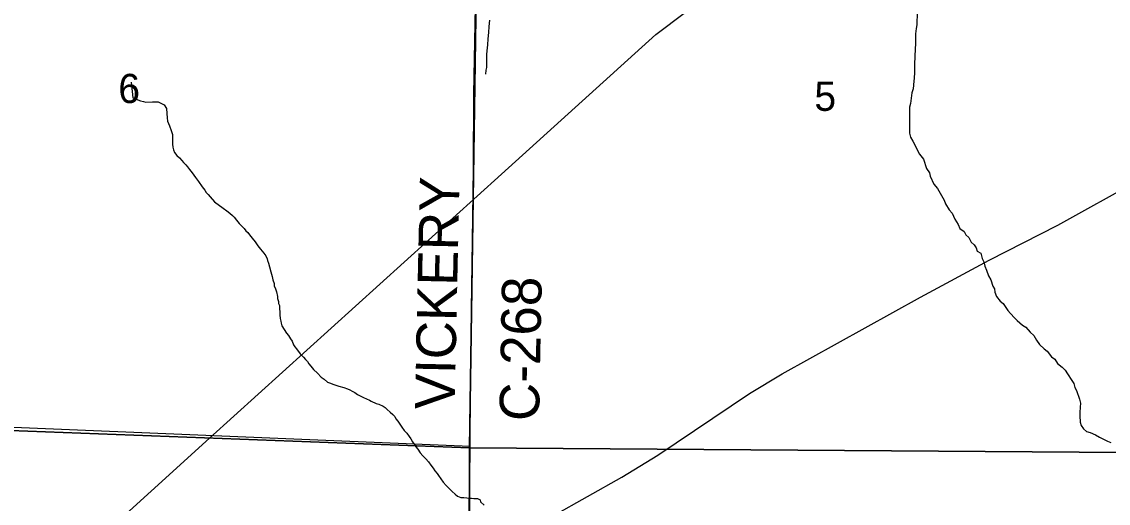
# Model space of a CAD drawing. Extents: x -8.5 to 18.7, y -20.3 to 7.
# Drawn here: x 12.261 to 15.375, y -1.005 to 0.375 of the extents above; entities that cross this region are included whole.
import ezdxf

# ---------------------------------------------------------------- set-up
doc = ezdxf.new("R2010")
doc.units = 0
for name, color, linetype in [('GM_X_County_Road', 7, 'Continuous'), ('GM_X_County_Road_Text', 7, 'Continuous'), ('GM_X_Minor_River', 7, 'Continuous'), ('GM_X_Rail_Line', 7, 'Continuous'), ('GM_X_Section', 7, 'Continuous'), ('GM_X_Section_Text', 7, 'Continuous'), ('GM_X_State_Route', 7, 'Continuous'), ('GM_X_Township_Road', 7, 'Continuous')]:
    doc.layers.add(name, color=color, linetype=linetype)

msp = doc.modelspace()

# ---------------------------------------------------------------- linework, layer by layer
at = {"layer": 'GM_X_County_Road'}
msp.add_lwpolyline([(13.5429, -1.1774), (13.5457, -1.1129), (13.546, -0.9367), (13.5466, -0.8416), (13.548, -0.6795), (13.55, -0.4503), (13.553, -0.2515), (13.5558, -0.0456), (13.5572, 0.1676), (13.5612, 0.3695), (13.5648, 0.5662), (13.5704, 0.8181), (13.5752, 1.0646), (13.5783, 1.1785), (13.5804, 1.1936)], dxfattribs=at)
at = {"layer": 'GM_X_Minor_River'}
for points in [[(13.6024, 0.3796), (13.6002, 0.3613), (13.5988, 0.3446), (13.5974, 0.3264), (13.5959, 0.3089), (13.5945, 0.2922), (13.5938, 0.2808), (13.5938, 0.2755), (13.5931, 0.2701), (13.5932, 0.2496), (13.5932, 0.2436), (13.5917, 0.2367), (13.591, 0.2253)], [(14.8276, 0.4028), (14.8263, 0.3664), (14.8248, 0.3557), (14.8226, 0.3405), (14.8227, 0.3185), (14.8221, 0.2911), (14.8214, 0.282), (14.8207, 0.2714), (14.82, 0.2577), (14.8201, 0.2296), (14.8187, 0.2136), (14.818, 0.2045), (14.8158, 0.1832), (14.8128, 0.1711), (14.8084, 0.1407), (14.8062, 0.13), (14.8055, 0.1125), (14.8058, 0.0556), (14.8089, 0.0442), (14.815, 0.0328), (14.8342, -0.0043), (14.8457, -0.0187), (14.8549, -0.046), (14.8633, -0.0581), (14.8649, -0.0672), (14.8756, -0.09), (14.8863, -0.1028), (14.897, -0.1225), (14.9047, -0.1362), (14.9093, -0.1468), (14.9193, -0.1642), (14.9284, -0.1733), (14.9353, -0.1907), (14.9453, -0.2059), (14.9499, -0.218), (14.9621, -0.2263), (14.9675, -0.2354), (14.9758, -0.2437), (14.9827, -0.2566), (14.9911, -0.2642), (14.9972, -0.2725), (14.9996, -0.2824), (15.0102, -0.2884), (15.0141, -0.3036), (15.0187, -0.3134), (15.0218, -0.3256), (15.0264, -0.3369), (15.0318, -0.3536), (15.0387, -0.365), (15.0449, -0.3824), (15.0495, -0.3908), (15.0503, -0.3999), (15.0549, -0.412), (15.0656, -0.4256), (15.074, -0.4324), (15.0877, -0.4529), (15.0954, -0.4612), (15.1068, -0.4733), (15.1144, -0.4816), (15.1297, -0.4945), (15.1388, -0.5005), (15.1511, -0.5149), (15.1617, -0.5239)], [(12.5746, 0.2015), (12.5801, 0.1575), (12.5893, 0.1529), (12.6022, 0.1484), (12.6106, 0.1462), (12.6166, 0.1447), (12.6364, 0.1456), (12.6523, 0.1456), (12.6691, 0.1366), (12.676, 0.126), (12.6775, 0.1123), (12.6784, 0.0994), (12.6792, 0.0903), (12.6846, 0.0767), (12.6899, 0.0638), (12.6938, 0.0524), (12.6939, 0.0243), (12.6947, 0.0152), (12.6963, 0.0083), (12.6994, 0), (12.7055, -0.0083), (12.7131, -0.0151), (12.72, -0.0227), (12.7253, -0.0287), (12.7314, -0.0355), (12.7368, -0.0408), (12.7421, -0.0484), (12.7498, -0.0583), (12.7597, -0.0711), (12.7681, -0.0832), (12.7788, -0.0984), (12.7857, -0.1075), (12.7895, -0.1143), (12.7956, -0.1203), (12.801, -0.1264), (12.8139, -0.1415), (12.8383, -0.1596), (12.849, -0.1672), (12.8581, -0.174), (12.865, -0.18), (12.8703, -0.1853), (12.8772, -0.1936), (12.8849, -0.2035), (12.8917, -0.211), (12.8986, -0.2178), (12.9039, -0.2239), (12.9093, -0.2292), (12.9146, -0.236), (12.9215, -0.2451), (12.9299, -0.2557), (12.9383, -0.267), (12.9452, -0.2769), (12.9505, -0.2829), (12.9551, -0.2882), (12.9605, -0.2958), (12.9643, -0.3041), (12.9659, -0.3094), (12.9682, -0.317), (12.9713, -0.3277), (12.9751, -0.3413), (12.9774, -0.3481), (12.979, -0.355), (12.9806, -0.3648), (12.9844, -0.3755), (12.9852, -0.3815), (12.989, -0.3906), (12.9914, -0.399), (12.9945, -0.4126), (12.9945, -0.4179), (12.9968, -0.4271), (12.9968, -0.4324), (12.9999, -0.4384), (13, -0.4468), (13.0008, -0.4574), (13.0008, -0.465), (13.0024, -0.4757), (13.0039, -0.4832), (13.0047, -0.4893), (13.007, -0.4961), (13.0132, -0.5067), (13.02, -0.5173), (13.0262, -0.5242), (13.0315, -0.534), (13.0361, -0.5408), (13.0407, -0.5507), (13.0438, -0.5567), (13.0484, -0.5628), (13.0598, -0.5764), (13.069, -0.5862), (13.0751, -0.5931), (13.0804, -0.5991), (13.0843, -0.6052), (13.0896, -0.612), (13.098, -0.6218), (13.1087, -0.6324), (13.1194, -0.6437), (13.1285, -0.6498), (13.1377, -0.6581), (13.143, -0.6603), (13.1559, -0.6648), (13.1704, -0.6693)], [(15.1617, -0.5239), (15.1694, -0.5376), (15.1786, -0.5497), (15.1915, -0.5625), (15.1999, -0.5693), (15.2129, -0.5852), (15.222, -0.592), (15.2297, -0.6049), (15.2434, -0.6147), (15.2518, -0.6238), (15.2587, -0.6344), (15.2709, -0.6533), (15.2763, -0.6617), (15.2794, -0.673), (15.2848, -0.6821), (15.2925, -0.7072), (15.2956, -0.7185), (15.2949, -0.7299), (15.2942, -0.7451), (15.2935, -0.755), (15.2951, -0.7725), (15.2982, -0.7823), (15.3043, -0.7922), (15.3134, -0.7997), (15.3233, -0.8027), (15.3385, -0.8095), (15.3499, -0.8155), (15.3735, -0.8268), (15.3827, -0.8313)], [(13.1704, -0.6693), (13.1848, -0.6738), (13.1947, -0.6768), (13.2015, -0.6798), (13.2084, -0.6836), (13.216, -0.6881), (13.2236, -0.6934), (13.2328, -0.6979), (13.2411, -0.7017), (13.2579, -0.7099), (13.2632, -0.7122), (13.2769, -0.719), (13.2845, -0.7212), (13.2974, -0.7265), (13.3028, -0.7302), (13.3089, -0.7363), (13.3173, -0.7438), (13.3249, -0.7506), (13.3302, -0.7567), (13.334, -0.7628), (13.3394, -0.7703), (13.3448, -0.7787), (13.3509, -0.787), (13.3578, -0.7968), (13.3646, -0.8044), (13.3715, -0.8135), (13.3761, -0.8203), (13.3814, -0.8294), (13.386, -0.8362), (13.3906, -0.843), (13.3967, -0.8498), (13.4029, -0.8604), (13.4105, -0.8688), (13.4196, -0.8778), (13.4273, -0.8869), (13.4342, -0.896), (13.4403, -0.9043), (13.4456, -0.9119), (13.4517, -0.9202), (13.4556, -0.9255), (13.4625, -0.9354), (13.4693, -0.9444), (13.4777, -0.9543), (13.4869, -0.9641), (13.4953, -0.9717), (13.5037, -0.9792), (13.5105, -0.9853), (13.5197, -0.9883), (13.5288, -0.989), (13.5371, -0.9897), (13.5432, -0.9904), (13.55, -0.9904), (13.5569, -0.9911), (13.5622, -0.9919), (13.5675, -0.9918), (13.5751, -0.9956), (13.5759, -1.0009), (13.5866, -1.0107)]]:
    msp.add_lwpolyline(points, dxfattribs=at)
at = {"layer": 'GM_X_Rail_Line'}
msp.add_lwpolyline([(9.8265, -3.4832), (9.9554, -3.3738), (10.2236, -3.1276), (10.7275, -2.6809), (11.4033, -2.0504), (11.764, -1.7469), (11.984, -1.5594), (12.7991, -0.8182), (13.6363, -0.0615), (14.079, 0.3384), (14.2522, 0.47), (14.4319, 0.6106), (14.5413, 0.6862), (15.5503, 1.4365), (16.5816, 2.231), (17.7899, 3.0985), (18.6545, 3.7446), (18.7413, 3.8103)], dxfattribs=at)
at = {"layer": 'GM_X_Section'}
for points in [[(11.5917, 1.2464), (13.5754, 1.2308), (13.5442, -0.8461), (11.5691, -0.7714)], [(13.5754, 1.2308), (13.5966, 1.2307), (15.5788, 1.2174), (15.5605, -0.8603), (13.5442, -0.8461)], [(11.5691, -0.7714), (13.5442, -0.8461), (13.5383, -2.851), (11.5391, -2.7686)], [(13.5442, -0.8461), (15.5605, -0.8603), (15.5425, -2.8599), (13.5383, -2.851)]]:
    msp.add_lwpolyline(points, close=True, dxfattribs=at)
at = {"layer": 'GM_X_State_Route'}
msp.add_lwpolyline([(13.7849, -1.0414), (13.9812, -0.9303), (14.0844, -0.8669), (14.347, -0.6902), (14.4407, -0.6341), (14.8373, -0.4147), (15.0342, -0.3081), (15.2305, -0.2077), (15.4645, -0.0776), (15.5685, -0.0156), (15.7241, 0.0825), (16.1569, 0.3571), (16.2382, 0.416), (16.4217, 0.5495), (16.581, 0.6707), (16.7661, 0.812), (16.8794, 0.8973), (16.9585, 0.9556), (17.019, 0.9978), (17.0758, 1.0347)], dxfattribs=at)
at = {"layer": 'GM_X_Township_Road'}
msp.add_line((11.5682, -0.7597), (13.5466, -0.8416), dxfattribs=at)

# ---------------------------------------------------------------- texts
at = {"layer": 'GM_X_County_Road_Text'}
for s, rotation, p in [('VICKERY', 88.7614, (13.5018, -0.7372)), ('C-268', 88.8978, (13.7439, -0.7703))]:
    msp.add_text(s, height=0.11364, rotation=rotation, dxfattribs=at).set_placement(p)
at = {"layer": 'GM_X_Section_Text'}
for s, p in [('6', (12.5381, 0.142)), ('5', (14.5331, 0.1197))]:
    msp.add_text(s, height=0.0837, rotation=0, dxfattribs=at).set_placement(p)

doc.saveas('drawing.dxf')
